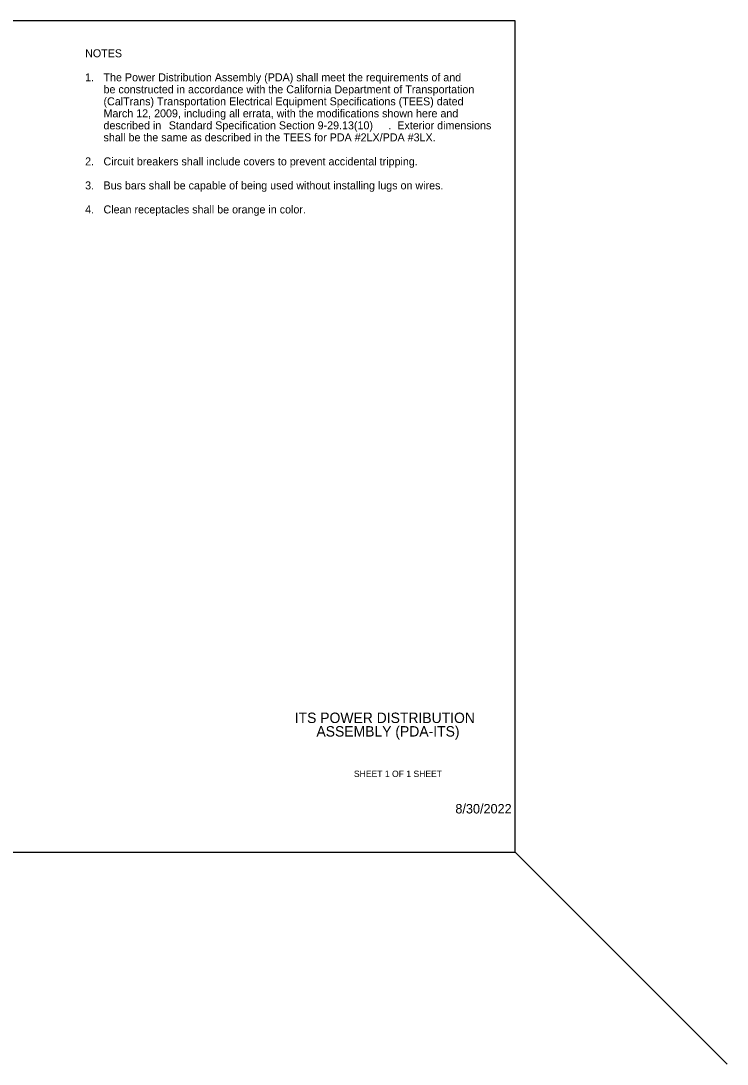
# Model space of a CAD drawing. Extents: x 99862 to 103680, y 99470 to 102076.
# Drawn here: x 101916 to 103680, y 99470 to 102076 of the extents above; entities that cross this region are included whole.
import ezdxf

# ---------------------------------------------------------------- set-up
doc = ezdxf.new("R2010")
doc.units = 0
for name, color, linetype in [('Level 1', 7, 'Continuous'), ('Level 15', 7, 'Continuous'), ('Level 20', 7, 'Continuous'), ('Level 60', 7, 'Continuous'), ('Level 62', 7, 'Continuous')]:
    doc.layers.add(name, color=color, linetype=linetype)

msp = doc.modelspace()

# ---------------------------------------------------------------- linework, layer by layer
at = {"layer": 'Level 1'}
msp.add_line((103150, 100000), (103680.3, 99469.7), dxfattribs=at)
msp.add_lwpolyline([(99862, 99999.5), (103151, 99999.5), (103151, 102075.5), (99862, 102075.5)], close=True, dxfattribs=at)
at = {"layer": 'Level 60'}
msp.add_line((103151, 102075.5), (103151, 102075.5), dxfattribs=at)

# ---------------------------------------------------------------- texts
at = {"layer": 'Level 15'}
msp.add_text('8/30/2022', height=23.62, dxfattribs=at).set_placement((103001.6, 100095.8))
at = {"layer": 'Level 20'}
for s, p in [('NOTES', (102076.8, 101984.5)), ('1.', (102076.8, 101924.5)), ('The Power Distribution Assembly (PDA) shall meet the requirements of and', (102122.7, 101924.5)), ('be constructed in accordance with the California Department of Transportation', (102122.7, 101894.5)), ('(CalTrans) Transportation Electrical Equipment Specifications (TEES) dated', (102122.7, 101864.5)), ('March 12, 2009, including all errata, with the modifications shown here and', (102122.7, 101834.5)), ('described in ', (102122.7, 101804.5)), ('Standard Specification Section 9-29.13(10)', (102285.8, 101804.5)), ('Exterior dimensions', (102856.5, 101804.5)), ('shall be the same as described in the TEES for PDA #2LX/PDA #3LX.', (102122.7, 101774.5)), ('.  ', (102833.8, 101804.5)), ('2.', (102076.8, 101714.5)), ('Circuit breakers shall include covers to prevent accidental tripping.', (102122.7, 101714.5)), ('3.', (102076.8, 101654.5)), ('Bus bars shall be capable of being used without installing lugs on wires.', (102122.7, 101654.5)), ('4.', (102076.8, 101594.5)), ('Clean receptacles shall be orange in color.', (102122.7, 101594.5))]:
    msp.add_text(s, height=20, dxfattribs=at).set_placement(p)
at = {"layer": 'Level 62'}
for s, height, p in [('ITS POWER DISTRIBUTION', 26, (102600.3, 100321.7)), ('ASSEMBLY (PDA-ITS)', 26, (102654.5, 100287.9)), ('SHEET 1 OF 1 SHEET', 16, (102748.2, 100186.8))]:
    msp.add_text(s, height=height, dxfattribs=at).set_placement(p)

doc.saveas('drawing.dxf')
